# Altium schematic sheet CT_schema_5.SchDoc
size 299 x 185 mm
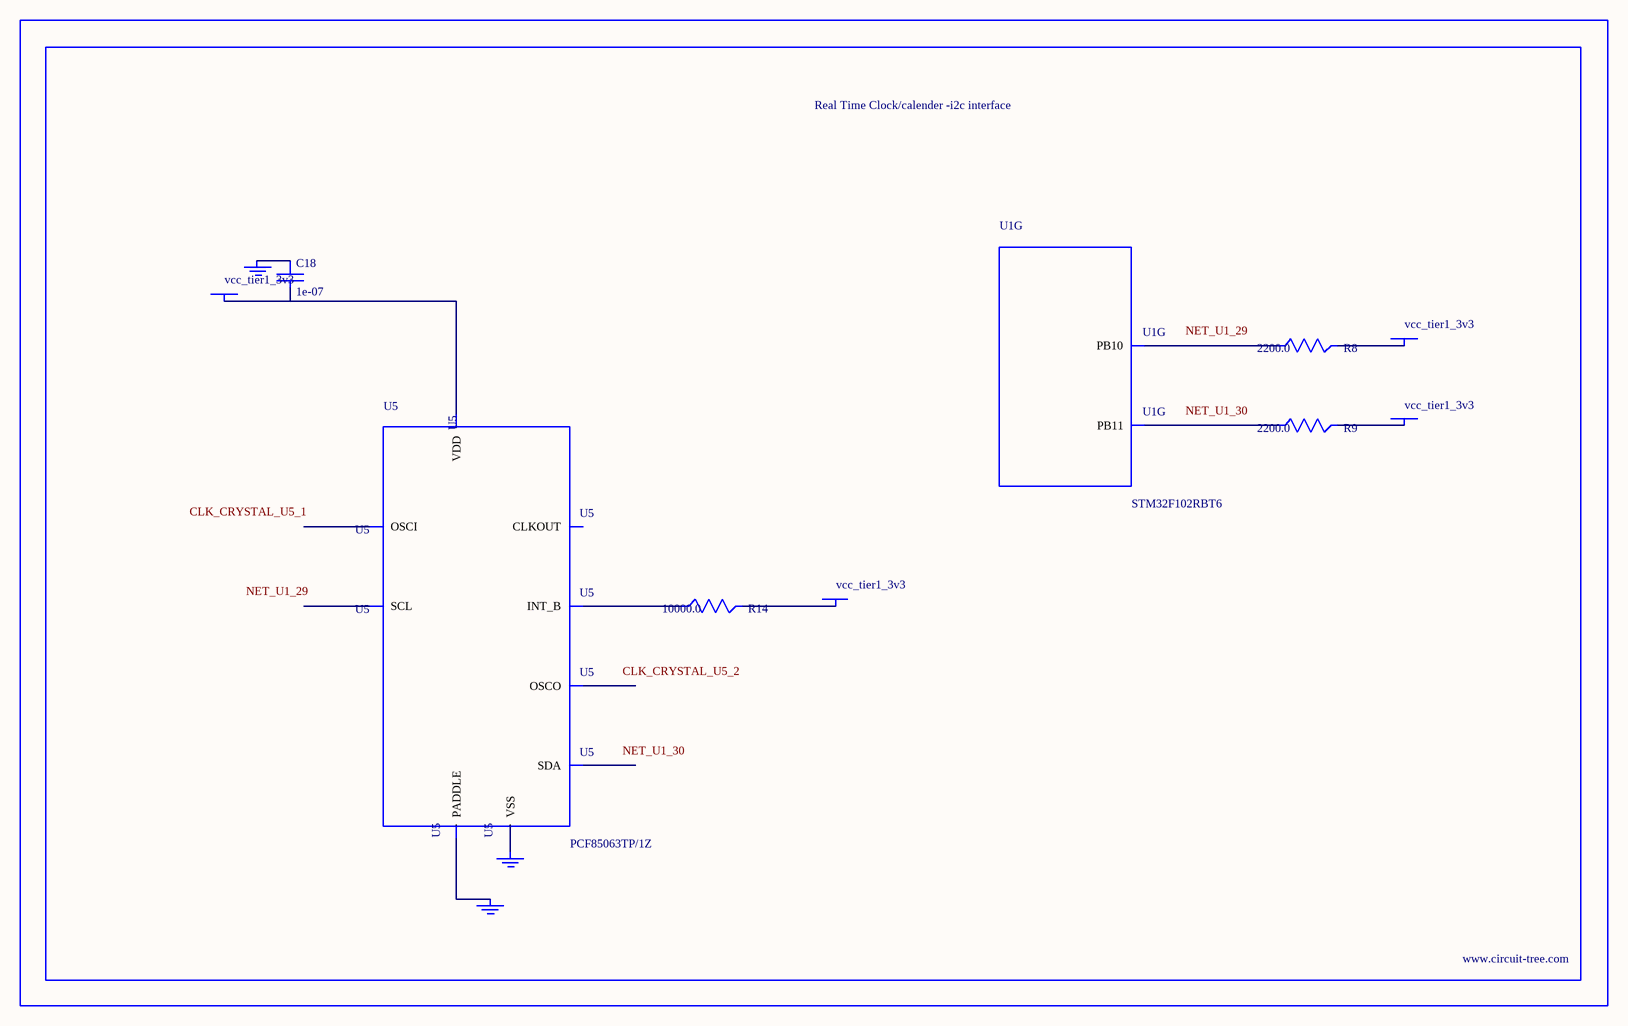
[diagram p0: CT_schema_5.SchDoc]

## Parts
BORDER4  (no value)
C18  1e-07  [C0402]
GND_INSTANCE_4_0  (no value)
GND_INSTANCE_4_1  (no value)
GND_INSTANCE_4_2  (no value)
POWER_INSTANCE_4_0  vcc_tier1_3v3
POWER_INSTANCE_4_1  vcc_tier1_3v3
POWER_INSTANCE_4_2  vcc_tier1_3v3
POWER_INSTANCE_4_3  vcc_tier1_3v3
R8  2200.0  [R0603]
R9  2200.0  [R0603]
R14  10000.0  [R0603]
U1  STM32F102RBT6  [LQFP64]  (part G of 7)
U5  PCF85063TP/1Z  [SON-8]

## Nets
NetC18_1: C18.1 GND_INSTANCE_4_0.0(GND)
NetC18_2: C18.2 POWER_INSTANCE_4_1.0(PWR) U5.8(VDD)
NetGND_INSTANCE_4_1_0: GND_INSTANCE_4_1.0(GND) U5.PAD(PADDLE)
NetGND_INSTANCE_4_2_0: GND_INSTANCE_4_2.0(GND) U5.4(VSS)
NetPOWER_INSTANCE_4_0_0: POWER_INSTANCE_4_0.0(PWR) R14.2
NetPOWER_INSTANCE_4_2_0: POWER_INSTANCE_4_2.0(PWR) R8.2
NetPOWER_INSTANCE_4_3_0: POWER_INSTANCE_4_3.0(PWR) R9.2
NetR8_1: R8.1 U1.29(PB10)
NetR9_1: R9.1 U1.30(PB11)
NetR14_1: R14.1 U5.3(INT_B)

Not connected (* = marked no-connect by the designer): U5 1(OSCI) 2(OSCO) 5(SDA) 6(SCL) 7(CLKOUT)

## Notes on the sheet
- Labels drawn without touching a wire or pin: CLK_CRYSTAL_U5_1, CLK_CRYSTAL_U5_2, NET_U1_29, NET_U1_30

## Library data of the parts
BORDER4 = BORDER_PAGE4
C18 = C0402C104K3RACTU
GND_INSTANCE_4_0-GND_INSTANCE_4_2 = GND
POWER_INSTANCE_4_0-POWER_INSTANCE_4_3 = PWR
R8 R9 = RC0603JR-072K2L
R14 = RC0603JR-0710KL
